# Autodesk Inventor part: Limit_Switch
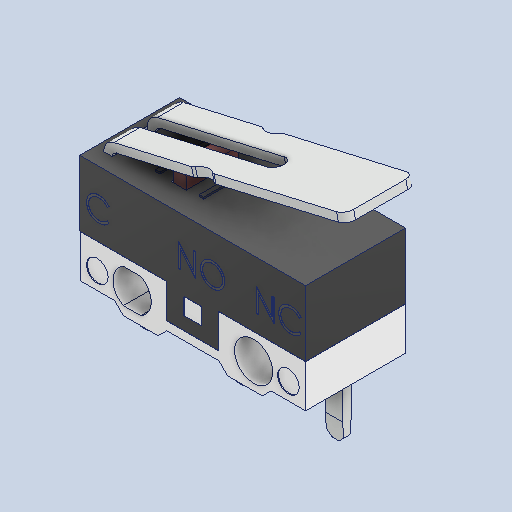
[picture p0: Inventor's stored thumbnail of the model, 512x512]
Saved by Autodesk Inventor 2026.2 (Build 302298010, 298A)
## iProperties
Created: 2022-04
Part Number: Limit_Switch
Material: Generic
Document SubType Name: Modeling
Designer: mel
Density: 1 g/cm^3
Appearance: Par défaut
Author: mel
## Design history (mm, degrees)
feature "Solid1"
feature "Solid2"
node "Solide1"
node "Solide2"
